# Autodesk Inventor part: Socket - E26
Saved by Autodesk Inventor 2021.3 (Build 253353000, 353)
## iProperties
Created: 2022-08
Part Number: Socket - E26
Material: Generic
Document SubType Name: Modeling
Designer: Administrator
Density: 1 g/cm^3
Appearance: Default
Title: Socket - E26
Author: Administrator
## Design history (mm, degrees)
feature "Socket - E26"
body "Solid1"
